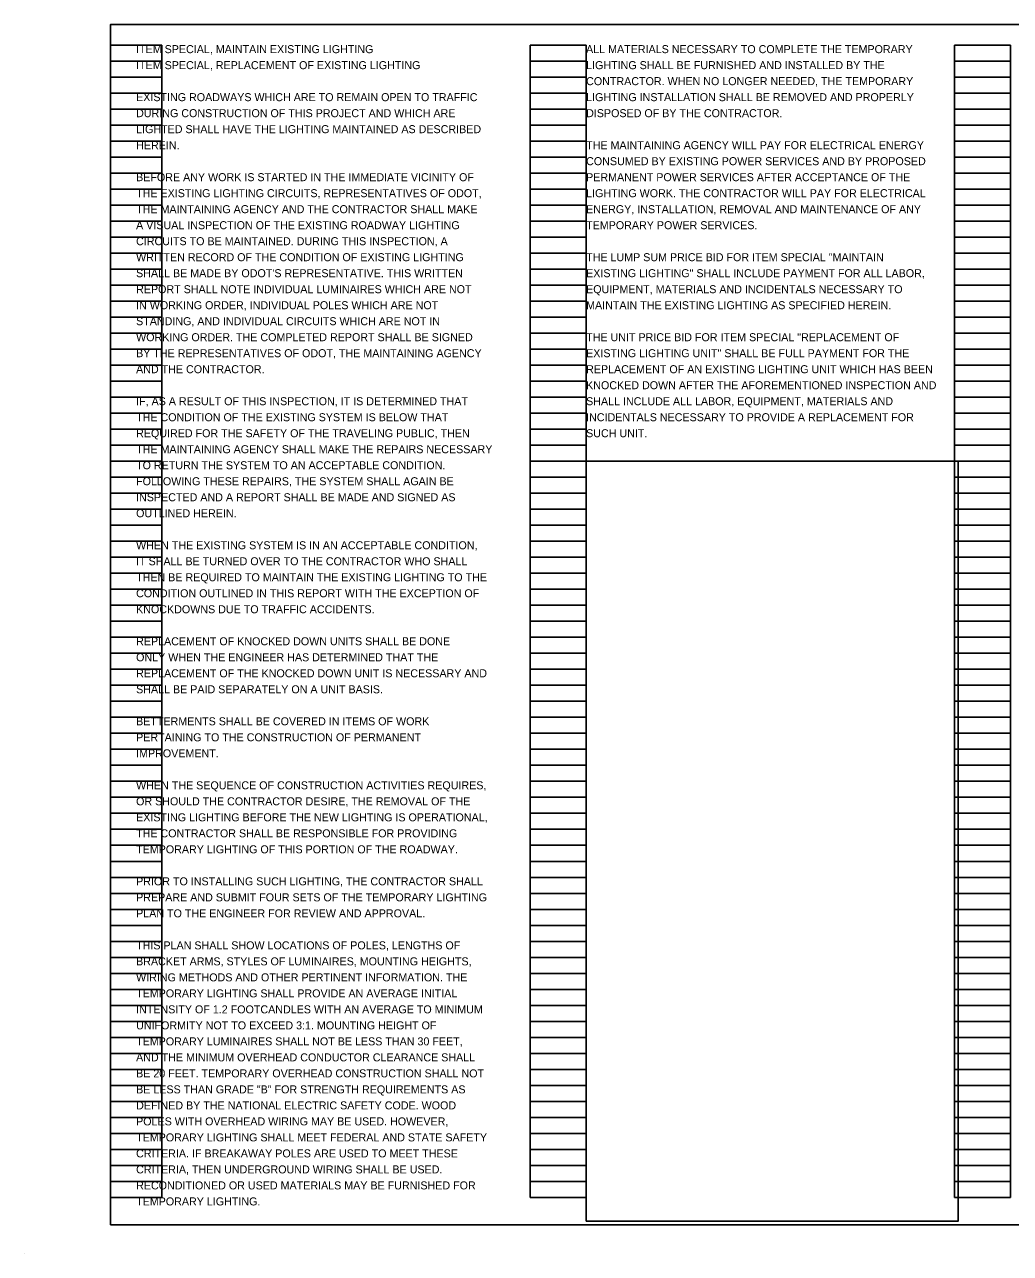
# Model space of a CAD drawing. Extents: x 0 to 2132911, y 0 to 658646.
# Drawn here: x 34 to 51.24, y 0 to 21.5 of the extents above; entities that cross this region are included whole.
import ezdxf

# ---------------------------------------------------------------- set-up
doc = ezdxf.new("R2010")
doc.units = 0
for name, color, linetype in [('SC_Scratch1', 7, 'Continuous'), ('SH_Data', 7, 'Continuous'), ('SH_Text', 7, 'Continuous')]:
    doc.layers.add(name, color=color, linetype=linetype)

msp = doc.modelspace()

# ---------------------------------------------------------------- linework, layer by layer
at = {"layer": 'SC_Scratch1'}
msp.add_lwpolyline([(35.5, 0.5), (66, 0.5), (66, 21.5), (35.5, 21.5)], close=True, dxfattribs=at)
at = {"layer": 'SH_Data'}
for p, q in [((35.5, 0.98), (35.5, 21.14)), ((35.5, 21.14), (36.4, 21.14)), ((36.4, 0.98), (36.4, 21.14)), ((42.84, 0.98), (42.84, 21.14)), ((42.84, 21.14), (43.82, 21.14)), ((43.82, 0.98), (43.82, 21.14)), ((50.26, 0.98), (50.26, 21.14)), ((50.26, 21.14), (51.24, 21.14)), ((51.24, 0.98), (51.24, 21.14)), ((35.5, 20.86), (36.4, 20.86)), ((42.84, 20.86), (43.82, 20.86)), ((50.26, 20.86), (51.24, 20.86)), ((35.5, 20.58), (36.4, 20.58)), ((42.84, 20.58), (43.82, 20.58)), ((50.26, 20.58), (51.24, 20.58)), ((35.5, 20.3), (36.4, 20.3)), ((42.84, 20.3), (43.82, 20.3)), ((50.26, 20.3), (51.24, 20.3)), ((35.5, 20.02), (36.4, 20.02)), ((42.84, 20.02), (43.82, 20.02)), ((50.26, 20.02), (51.24, 20.02)), ((35.5, 19.74), (36.4, 19.74)), ((42.84, 19.74), (43.82, 19.74)), ((50.26, 19.74), (51.24, 19.74)), ((35.5, 19.46), (36.4, 19.46)), ((42.84, 19.46), (43.82, 19.46)), ((50.26, 19.46), (51.24, 19.46)), ((35.5, 19.18), (36.4, 19.18)), ((42.84, 19.18), (43.82, 19.18)), ((50.26, 19.18), (51.24, 19.18)), ((35.5, 18.9), (36.4, 18.9)), ((42.84, 18.9), (43.82, 18.9)), ((50.26, 18.9), (51.24, 18.9)), ((35.5, 18.62), (36.4, 18.62)), ((42.84, 18.62), (43.82, 18.62)), ((50.26, 18.62), (51.24, 18.62)), ((35.5, 18.34), (36.4, 18.34)), ((42.84, 18.34), (43.82, 18.34)), ((50.26, 18.34), (51.24, 18.34)), ((35.5, 18.06), (36.4, 18.06)), ((42.84, 18.06), (43.82, 18.06)), ((50.26, 18.06), (51.24, 18.06)), ((35.5, 17.78), (36.4, 17.78)), ((42.84, 17.78), (43.82, 17.78)), ((50.26, 17.78), (51.24, 17.78)), ((35.5, 17.5), (36.4, 17.5)), ((42.84, 17.5), (43.82, 17.5)), ((50.26, 17.5), (51.24, 17.5)), ((35.5, 17.22), (36.4, 17.22)), ((42.84, 17.22), (43.82, 17.22)), ((50.26, 17.22), (51.24, 17.22)), ((35.5, 16.94), (36.4, 16.94)), ((42.84, 16.94), (43.82, 16.94)), ((50.26, 16.94), (51.24, 16.94)), ((35.5, 16.66), (36.4, 16.66)), ((42.84, 16.66), (43.82, 16.66)), ((50.26, 16.66), (51.24, 16.66)), ((35.5, 16.38), (36.4, 16.38)), ((42.84, 16.38), (43.82, 16.38)), ((50.26, 16.38), (51.24, 16.38)), ((35.5, 16.1), (36.4, 16.1)), ((42.84, 16.1), (43.82, 16.1)), ((50.26, 16.1), (51.24, 16.1)), ((35.5, 15.82), (36.4, 15.82)), ((42.84, 15.82), (43.82, 15.82)), ((50.26, 15.82), (51.24, 15.82)), ((35.5, 15.54), (36.4, 15.54)), ((42.84, 15.54), (43.82, 15.54)), ((50.26, 15.54), (51.24, 15.54)), ((35.5, 15.26), (36.4, 15.26)), ((42.84, 15.26), (43.82, 15.26)), ((50.26, 15.26), (51.24, 15.26)), ((35.5, 14.98), (36.4, 14.98)), ((42.84, 14.98), (43.82, 14.98)), ((50.26, 14.98), (51.24, 14.98)), ((35.5, 14.7), (36.4, 14.7)), ((42.84, 14.7), (43.82, 14.7)), ((50.26, 14.7), (51.24, 14.7)), ((35.5, 14.42), (36.4, 14.42)), ((42.84, 14.42), (43.82, 14.42)), ((50.26, 14.42), (51.24, 14.42)), ((35.5, 14.14), (36.4, 14.14)), ((42.84, 14.14), (43.82, 14.14)), ((50.26, 14.14), (51.24, 14.14)), ((35.5, 13.86), (36.4, 13.86)), ((42.84, 13.86), (43.82, 13.86)), ((50.26, 13.86), (51.24, 13.86)), ((35.5, 13.58), (36.4, 13.58)), ((42.84, 13.58), (43.82, 13.58)), ((50.26, 13.58), (51.24, 13.58)), ((35.5, 13.3), (36.4, 13.3)), ((42.84, 13.3), (43.82, 13.3)), ((50.26, 13.3), (51.24, 13.3)), ((35.5, 13.02), (36.4, 13.02)), ((42.84, 13.02), (43.82, 13.02)), ((50.26, 13.02), (51.24, 13.02)), ((35.5, 12.74), (36.4, 12.74)), ((42.84, 12.74), (43.82, 12.74)), ((50.26, 12.74), (51.24, 12.74)), ((35.5, 12.46), (36.4, 12.46)), ((42.84, 12.46), (43.82, 12.46)), ((50.26, 12.46), (51.24, 12.46)), ((35.5, 12.18), (36.4, 12.18)), ((42.84, 12.18), (43.82, 12.18)), ((50.26, 12.18), (51.24, 12.18)), ((35.5, 11.9), (36.4, 11.9)), ((42.84, 11.9), (43.82, 11.9)), ((50.26, 11.9), (51.24, 11.9)), ((35.5, 11.62), (36.4, 11.62)), ((42.84, 11.62), (43.82, 11.62)), ((50.26, 11.62), (51.24, 11.62)), ((35.5, 11.34), (36.4, 11.34)), ((42.84, 11.34), (43.82, 11.34)), ((50.26, 11.34), (51.24, 11.34)), ((35.5, 11.06), (36.4, 11.06)), ((42.84, 11.06), (43.82, 11.06)), ((50.26, 11.06), (51.24, 11.06)), ((35.5, 10.78), (36.4, 10.78)), ((42.84, 10.78), (43.82, 10.78)), ((50.26, 10.78), (51.24, 10.78)), ((35.5, 10.5), (36.4, 10.5)), ((42.84, 10.5), (43.82, 10.5)), ((50.26, 10.5), (51.24, 10.5)), ((35.5, 10.22), (36.4, 10.22)), ((42.84, 10.22), (43.82, 10.22)), ((50.26, 10.22), (51.24, 10.22)), ((35.5, 9.94), (36.4, 9.94)), ((42.84, 9.94), (43.82, 9.94)), ((50.26, 9.94), (51.24, 9.94)), ((35.5, 9.66), (36.4, 9.66)), ((42.84, 9.66), (43.82, 9.66)), ((50.26, 9.66), (51.24, 9.66)), ((35.5, 9.38), (36.4, 9.38)), ((42.84, 9.38), (43.82, 9.38)), ((50.26, 9.38), (51.24, 9.38)), ((35.5, 9.1), (36.4, 9.1)), ((42.84, 9.1), (43.82, 9.1)), ((50.26, 9.1), (51.24, 9.1)), ((35.5, 8.82), (36.4, 8.82)), ((42.84, 8.82), (43.82, 8.82)), ((50.26, 8.82), (51.24, 8.82)), ((35.5, 8.54), (36.4, 8.54)), ((42.84, 8.54), (43.82, 8.54)), ((50.26, 8.54), (51.24, 8.54)), ((35.5, 8.26), (36.4, 8.26)), ((42.84, 8.26), (43.82, 8.26)), ((50.26, 8.26), (51.24, 8.26)), ((35.5, 7.98), (36.4, 7.98)), ((42.84, 7.98), (43.82, 7.98)), ((50.26, 7.98), (51.24, 7.98)), ((35.5, 7.7), (36.4, 7.7)), ((42.84, 7.7), (43.82, 7.7)), ((50.26, 7.7), (51.24, 7.7)), ((35.5, 7.42), (36.4, 7.42)), ((42.84, 7.42), (43.82, 7.42)), ((50.26, 7.42), (51.24, 7.42)), ((35.5, 7.14), (36.4, 7.14)), ((42.84, 7.14), (43.82, 7.14)), ((50.26, 7.14), (51.24, 7.14)), ((35.5, 6.86), (36.4, 6.86)), ((42.84, 6.86), (43.82, 6.86)), ((50.26, 6.86), (51.24, 6.86)), ((35.5, 6.58), (36.4, 6.58)), ((42.84, 6.58), (43.82, 6.58)), ((50.26, 6.58), (51.24, 6.58)), ((35.5, 6.3), (36.4, 6.3)), ((42.84, 6.3), (43.82, 6.3)), ((50.26, 6.3), (51.24, 6.3)), ((35.5, 6.02), (36.4, 6.02)), ((42.84, 6.02), (43.82, 6.02)), ((50.26, 6.02), (51.24, 6.02)), ((35.5, 5.74), (36.4, 5.74)), ((42.84, 5.74), (43.82, 5.74)), ((50.26, 5.74), (51.24, 5.74)), ((35.5, 5.46), (36.4, 5.46)), ((42.84, 5.46), (43.82, 5.46)), ((50.26, 5.46), (51.24, 5.46)), ((35.5, 5.18), (36.4, 5.18)), ((42.84, 5.18), (43.82, 5.18)), ((50.26, 5.18), (51.24, 5.18)), ((35.5, 4.9), (36.4, 4.9)), ((42.84, 4.9), (43.82, 4.9)), ((50.26, 4.9), (51.24, 4.9)), ((35.5, 4.62), (36.4, 4.62)), ((42.84, 4.62), (43.82, 4.62)), ((50.26, 4.62), (51.24, 4.62)), ((35.5, 4.34), (36.4, 4.34)), ((42.84, 4.34), (43.82, 4.34)), ((50.26, 4.34), (51.24, 4.34)), ((35.5, 4.06), (36.4, 4.06)), ((42.84, 4.06), (43.82, 4.06)), ((50.26, 4.06), (51.24, 4.06)), ((35.5, 3.78), (36.4, 3.78)), ((42.84, 3.78), (43.82, 3.78)), ((50.26, 3.78), (51.24, 3.78)), ((35.5, 3.5), (36.4, 3.5)), ((42.84, 3.5), (43.82, 3.5)), ((50.26, 3.5), (51.24, 3.5)), ((35.5, 3.22), (36.4, 3.22)), ((42.84, 3.22), (43.82, 3.22)), ((50.26, 3.22), (51.24, 3.22)), ((35.5, 2.94), (36.4, 2.94)), ((42.84, 2.94), (43.82, 2.94)), ((50.26, 2.94), (51.24, 2.94)), ((35.5, 2.66), (36.4, 2.66)), ((42.84, 2.66), (43.82, 2.66)), ((50.26, 2.66), (51.24, 2.66)), ((35.5, 2.38), (36.4, 2.38)), ((42.84, 2.38), (43.82, 2.38)), ((50.26, 2.38), (51.24, 2.38)), ((35.5, 2.1), (36.4, 2.1)), ((42.84, 2.1), (43.82, 2.1)), ((50.26, 2.1), (51.24, 2.1)), ((35.5, 1.82), (36.4, 1.82)), ((42.84, 1.82), (43.82, 1.82)), ((50.26, 1.82), (51.24, 1.82)), ((35.5, 1.54), (36.4, 1.54)), ((42.84, 1.54), (43.82, 1.54)), ((50.26, 1.54), (51.24, 1.54)), ((35.5, 1.26), (36.4, 1.26)), ((42.84, 1.26), (43.82, 1.26)), ((50.26, 1.26), (51.24, 1.26)), ((35.5, 0.98), (36.4, 0.98)), ((42.84, 0.98), (43.82, 0.98)), ((50.26, 0.98), (51.24, 0.98)), ((34, 0), (34, 0))]:
    msp.add_line(p, q, dxfattribs=at)
at = {"layer": 'SH_Text'}
msp.add_lwpolyline([(43.82, 0.564), (50.324, 0.564), (50.324, 13.86), (43.82, 13.86)], close=True, dxfattribs=at)

# ---------------------------------------------------------------- texts
for s, p in [('ITEM SPECIAL, MAINTAIN EXISTING LIGHTING', (35.95, 21)), ('ALL MATERIALS NECESSARY TO COMPLETE THE TEMPORARY', (43.82, 21)), ('ITEM SPECIAL, REPLACEMENT OF EXISTING LIGHTING', (35.95, 20.72)), ('LIGHTING SHALL BE FURNISHED AND INSTALLED BY THE', (43.82, 20.72)), ('CONTRACTOR. WHEN NO LONGER NEEDED, THE TEMPORARY', (43.82, 20.44)), ('EXISTING ROADWAYS WHICH ARE TO REMAIN OPEN TO TRAFFIC', (35.95, 20.16)), ('LIGHTING INSTALLATION SHALL BE REMOVED AND PROPERLY', (43.82, 20.16)), ('DURING CONSTRUCTION OF THIS PROJECT AND WHICH ARE', (35.95, 19.88)), ('DISPOSED OF BY THE CONTRACTOR.', (43.82, 19.88)), ('LIGHTED SHALL HAVE THE LIGHTING MAINTAINED AS DESCRIBED', (35.95, 19.6)), ('HEREIN.', (35.95, 19.32)), ('THE MAINTAINING AGENCY WILL PAY FOR ELECTRICAL ENERGY', (43.82, 19.32)), ('CONSUMED BY EXISTING POWER SERVICES AND BY PROPOSED', (43.82, 19.04)), ('BEFORE ANY WORK IS STARTED IN THE IMMEDIATE VICINITY OF', (35.95, 18.76)), ('PERMANENT POWER SERVICES AFTER ACCEPTANCE OF THE', (43.82, 18.76)), ('THE EXISTING LIGHTING CIRCUITS, REPRESENTATIVES OF ODOT,', (35.95, 18.48)), ('LIGHTING WORK. THE CONTRACTOR WILL PAY FOR ELECTRICAL', (43.82, 18.48)), ('THE MAINTAINING AGENCY AND THE CONTRACTOR SHALL MAKE', (35.95, 18.2)), ('ENERGY, INSTALLATION, REMOVAL AND MAINTENANCE OF ANY', (43.82, 18.2)), ('A VISUAL INSPECTION OF THE EXISTING ROADWAY LIGHTING', (35.95, 17.92)), ('TEMPORARY POWER SERVICES.', (43.82, 17.92)), ('CIRCUITS TO BE MAINTAINED. DURING THIS INSPECTION, A', (35.95, 17.64)), ('WRITTEN RECORD OF THE CONDITION OF EXISTING LIGHTING', (35.95, 17.36)), ('THE LUMP SUM PRICE BID FOR ITEM SPECIAL "MAINTAIN', (43.82, 17.36)), ("SHALL BE MADE BY ODOT'S REPRESENTATIVE. THIS WRITTEN", (35.95, 17.08)), ('EXISTING LIGHTING" SHALL INCLUDE PAYMENT FOR ALL LABOR,', (43.82, 17.08)), ('REPORT SHALL NOTE INDIVIDUAL LUMINAIRES WHICH ARE NOT', (35.95, 16.8)), ('EQUIPMENT, MATERIALS AND INCIDENTALS NECESSARY TO', (43.82, 16.8)), ('IN WORKING ORDER, INDIVIDUAL POLES WHICH ARE NOT', (35.95, 16.52)), ('MAINTAIN THE EXISTING LIGHTING AS SPECIFIED HEREIN.', (43.82, 16.52)), ('STANDING, AND INDIVIDUAL CIRCUITS WHICH ARE NOT IN', (35.95, 16.24)), ('WORKING ORDER. THE COMPLETED REPORT SHALL BE SIGNED', (35.95, 15.96)), ('THE UNIT PRICE BID FOR ITEM SPECIAL "REPLACEMENT OF', (43.82, 15.96)), ('BY THE REPRESENTATIVES OF ODOT, THE MAINTAINING AGENCY', (35.95, 15.68)), ('EXISTING LIGHTING UNIT" SHALL BE FULL PAYMENT FOR THE', (43.82, 15.68)), ('AND THE CONTRACTOR.', (35.95, 15.4)), ('REPLACEMENT OF AN EXISTING LIGHTING UNIT WHICH HAS BEEN', (43.82, 15.4)), ('KNOCKED DOWN AFTER THE AFOREMENTIONED INSPECTION AND', (43.82, 15.12)), ('IF, AS A RESULT OF THIS INSPECTION, IT IS DETERMINED THAT', (35.95, 14.84)), ('SHALL INCLUDE ALL LABOR, EQUIPMENT, MATERIALS AND', (43.82, 14.84)), ('THE CONDITION OF THE EXISTING SYSTEM IS BELOW THAT', (35.95, 14.56)), ('INCIDENTALS NECESSARY TO PROVIDE A REPLACEMENT FOR', (43.82, 14.56)), ('REQUIRED FOR THE SAFETY OF THE TRAVELING PUBLIC, THEN', (35.95, 14.28)), ('SUCH UNIT.', (43.82, 14.28)), ('THE MAINTAINING AGENCY SHALL MAKE THE REPAIRS NECESSARY', (35.95, 14)), ('TO RETURN THE SYSTEM TO AN ACCEPTABLE CONDITION.', (35.95, 13.72)), ('FOLLOWING THESE REPAIRS, THE SYSTEM SHALL AGAIN BE', (35.95, 13.44)), ('INSPECTED AND A REPORT SHALL BE MADE AND SIGNED AS', (35.95, 13.16)), ('OUTLINED HEREIN.', (35.95, 12.88)), ('WHEN THE EXISTING SYSTEM IS IN AN ACCEPTABLE CONDITION,', (35.95, 12.32)), ('IT SHALL BE TURNED OVER TO THE CONTRACTOR WHO SHALL', (35.95, 12.04)), ('THEN BE REQUIRED TO MAINTAIN THE EXISTING LIGHTING TO THE', (35.95, 11.76)), ('CONDITION OUTLINED IN THIS REPORT WITH THE EXCEPTION OF', (35.95, 11.48)), ('KNOCKDOWNS DUE TO TRAFFIC ACCIDENTS.', (35.95, 11.2)), ('REPLACEMENT OF KNOCKED DOWN UNITS SHALL BE DONE', (35.95, 10.64)), ('ONLY WHEN THE ENGINEER HAS DETERMINED THAT THE', (35.95, 10.36)), ('REPLACEMENT OF THE KNOCKED DOWN UNIT IS NECESSARY AND', (35.95, 10.08)), ('SHALL BE PAID SEPARATELY ON A UNIT BASIS.', (35.95, 9.8)), ('BETTERMENTS SHALL BE COVERED IN ITEMS OF WORK', (35.95, 9.24)), ('PERTAINING TO THE CONSTRUCTION OF PERMANENT', (35.95, 8.96)), ('IMPROVEMENT.', (35.95, 8.68)), ('WHEN THE SEQUENCE OF CONSTRUCTION ACTIVITIES REQUIRES,', (35.95, 8.12)), ('OR SHOULD THE CONTRACTOR DESIRE, THE REMOVAL OF THE', (35.95, 7.84)), ('EXISTING LIGHTING BEFORE THE NEW LIGHTING IS OPERATIONAL,', (35.95, 7.56)), ('THE CONTRACTOR SHALL BE RESPONSIBLE FOR PROVIDING', (35.95, 7.28)), ('TEMPORARY LIGHTING OF THIS PORTION OF THE ROADWAY.', (35.95, 7)), ('PRIOR TO INSTALLING SUCH LIGHTING, THE CONTRACTOR SHALL', (35.95, 6.44)), ('PREPARE AND SUBMIT FOUR SETS OF THE TEMPORARY LIGHTING', (35.95, 6.16)), ('PLAN TO THE ENGINEER FOR REVIEW AND APPROVAL.', (35.95, 5.88)), ('THIS PLAN SHALL SHOW LOCATIONS OF POLES, LENGTHS OF', (35.95, 5.32)), ('BRACKET ARMS, STYLES OF LUMINAIRES, MOUNTING HEIGHTS,', (35.95, 5.04)), ('WIRING METHODS AND OTHER PERTINENT INFORMATION. THE', (35.95, 4.76)), ('TEMPORARY LIGHTING SHALL PROVIDE AN AVERAGE INITIAL', (35.95, 4.48)), ('INTENSITY OF 1.2 FOOTCANDLES WITH AN AVERAGE TO MINIMUM', (35.95, 4.2)), ('UNIFORMITY NOT TO EXCEED 3:1. MOUNTING HEIGHT OF', (35.95, 3.92)), ('TEMPORARY LUMINAIRES SHALL NOT BE LESS THAN 30 FEET,', (35.95, 3.64)), ('AND THE MINIMUM OVERHEAD CONDUCTOR CLEARANCE SHALL', (35.95, 3.36)), ('BE 20 FEET. TEMPORARY OVERHEAD CONSTRUCTION SHALL NOT', (35.95, 3.08)), ('BE LESS THAN GRADE "B" FOR STRENGTH REQUIREMENTS AS', (35.95, 2.8)), ('DEFINED BY THE NATIONAL ELECTRIC SAFETY CODE. WOOD', (35.95, 2.52)), ('POLES WITH OVERHEAD WIRING MAY BE USED. HOWEVER,', (35.95, 2.24)), ('TEMPORARY LIGHTING SHALL MEET FEDERAL AND STATE SAFETY', (35.95, 1.96)), ('CRITERIA. IF BREAKAWAY POLES ARE USED TO MEET THESE', (35.95, 1.68)), ('CRITERIA, THEN UNDERGROUND WIRING SHALL BE USED.', (35.95, 1.4)), ('RECONDITIONED OR USED MATERIALS MAY BE FURNISHED FOR', (35.95, 1.12)), ('TEMPORARY LIGHTING.', (35.95, 0.84))]:
    msp.add_text(s, height=0.14, dxfattribs=at).set_placement(p)

doc.saveas('drawing.dxf')
